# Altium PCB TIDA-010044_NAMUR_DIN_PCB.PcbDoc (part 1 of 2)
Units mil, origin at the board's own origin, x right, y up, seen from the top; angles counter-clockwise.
Board outline 1290 x 2860 mil, 2 copper layers (Top Layer, Bottom Layer), stack 62 mil thick; 85 components, 49 nets, 226 pads, 57 vias.
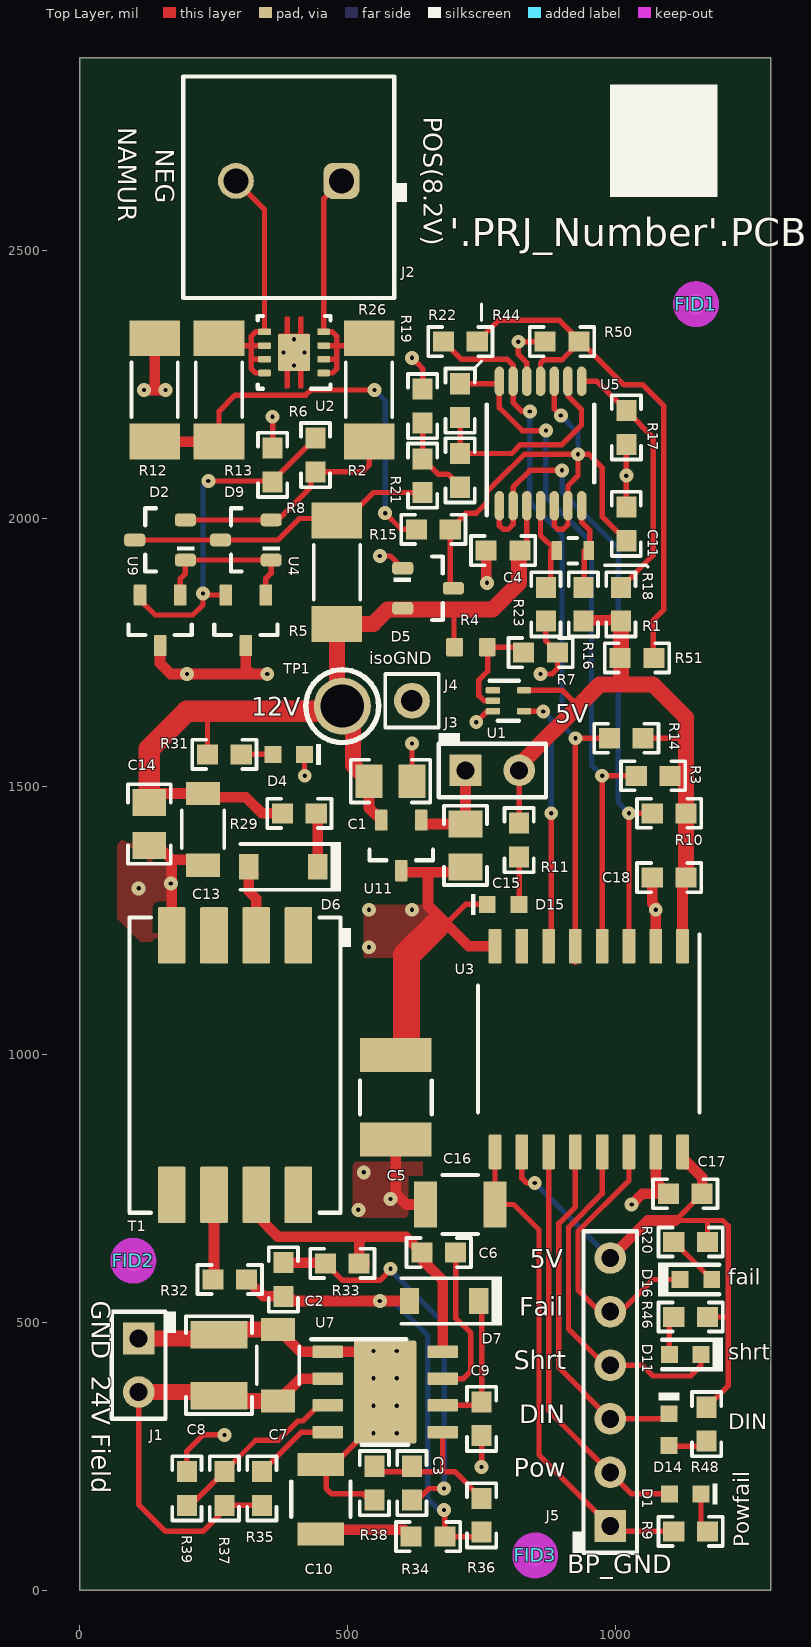
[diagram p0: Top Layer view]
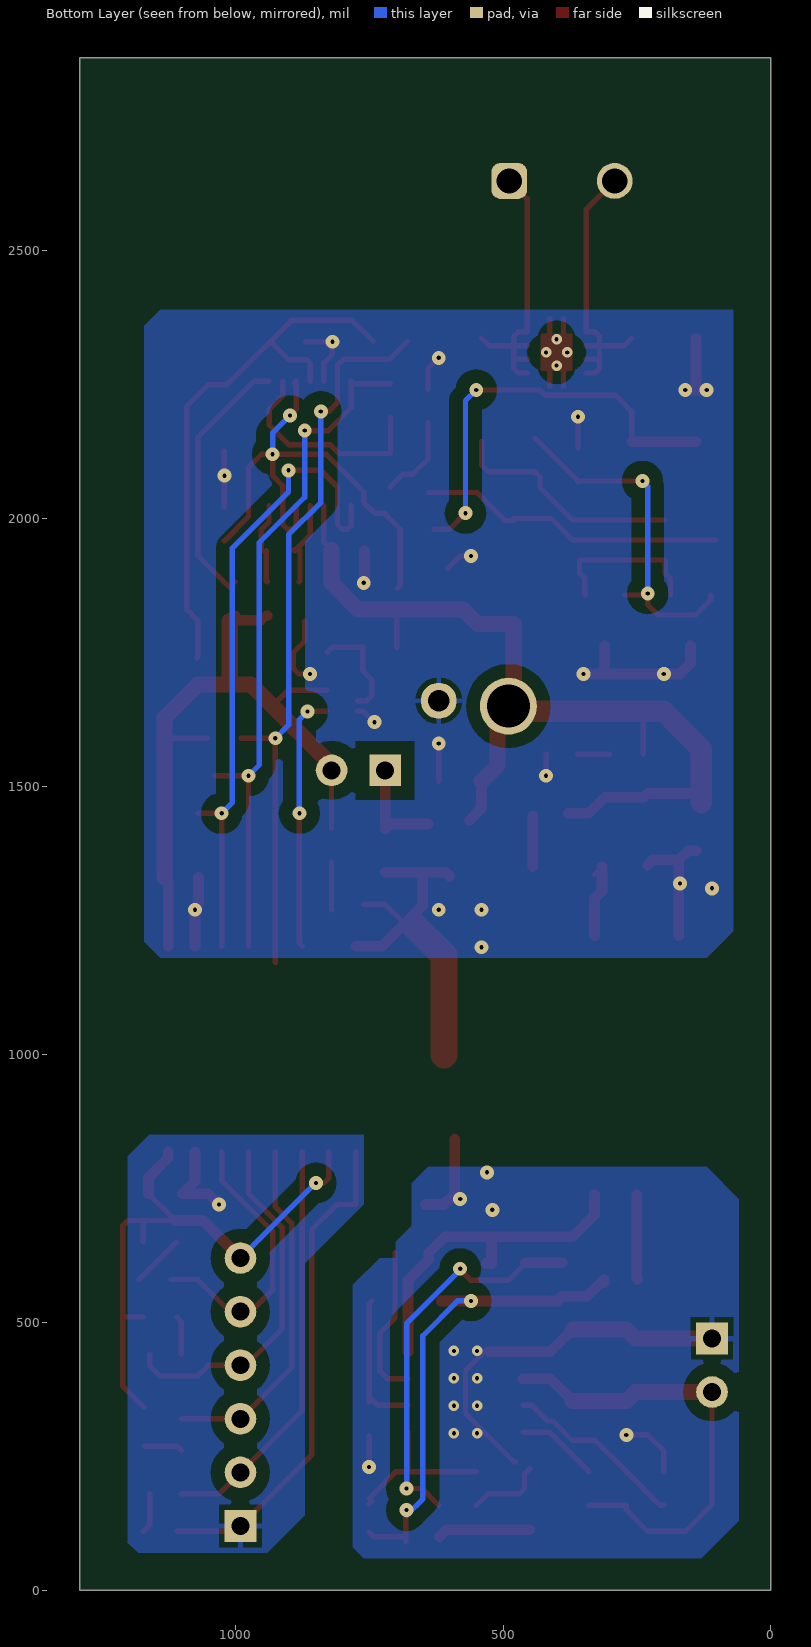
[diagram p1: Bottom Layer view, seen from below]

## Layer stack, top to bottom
Top Solder: solder mask 0.4, Solder Resist, Dk 3.5
Top Layer: signal copper 1.4
Dielectric1: core 59.2, FR-4, Dk 4.8
Bottom Layer: signal copper 1.4
Bottom Solder: solder mask 0.4, Solder Resist, Dk 3.5

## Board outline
0,0 1290,0 1290,2860 0,2860

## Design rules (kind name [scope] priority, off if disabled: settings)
AcuteAngle [All] p1: minimum=4.50000000000000E+0001 checktracksonly=FALSE
AssemblyTestPointUsage [All] p1: valid=2
BoardOutlineClearance BoardOutlineClearance_MountingHoles [OnCopper and InComponentClass('Mounting Holes')] p1: gap=40 ignorepadtopadclearanceinfootprint=FALSE
BoardOutlineClearance BoardOutlineClearance_Poly [OnCopper and IsPoly] p2: gap=25 ignorepadtopadclearanceinfootprint=FALSE
BoardOutlineClearance [OnCopper and Not InComponentClass('Logo') and not InComponentClass('FiducialMark') and not InRegion(1000,500,4000,800) and not InPoly] p3: gap=75 ignorepadtopadclearanceinfootprint=FALSE
Clearance Clearance_Keepouts [((IsTrack Or IsArc) And Not InPoly) And IsFree and IsKeepOut vs ((IsTrack Or IsArc) And Not InPoly) And IsFree and IsKeepOut] p1: gap=0 ignorepadtopadclearanceinfootprint=FALSE
Clearance Clearance_Poly [InPolygon] p2: gap=25 ignorepadtopadclearanceinfootprint=FALSE except(0: Arc-Hole Track-Hole SMDPad-Hole THPad-Hole Via-Hole Fill-Hole Poly-Hole Region-Hole Text-Hole)
Clearance Clearance_FiducialMark [IsKeepOut and InComponentClass('FiducialMark') vs IsPad and InComponentClass('FiducialMark')] p3: gap=0 ignorepadtopadclearanceinfootprint=FALSE
Clearance [All] p4: gap=7.87 ignorepadtopadclearanceinfootprint=FALSE except(0: Arc-Hole Track-Hole SMDPad-Hole THPad-Hole Via-Hole Fill-Hole Poly-Hole Region-Hole Text-Hole)
ComponentClearance ComponentClearance_MountingHoles_FiducialMarks [InComponentClass('Mounting Holes') vs InComponentClass('FiducialMark')] p1: gap=50 collisioncheckmode=3 verticalgap=10 showdistances=FALSE
ComponentClearance ComponentClearance_Shunt [InComponentClass('Header') vs InComponentClass('Shunt')] p2: gap=0 collisioncheckmode=3 verticalgap=0 showdistances=FALSE
ComponentClearance ComponentClearance_Logo [InComponentClass('Logo')] p3: gap=50 collisioncheckmode=3 verticalgap=10 showdistances=FALSE
ComponentClearance ComponentClearance_ScrewToNut [(HasFootprint('NY PMS 440 0025 PH')) vs (HasFootprint('Keystone_1902C'))] p4: gap=5 collisioncheckmode=3 verticalgap=10 showdistances=FALSE
ComponentClearance ComponentClearance_MountingHoles [InComponentClass('Mounting Holes')] p5: gap=250 collisioncheckmode=3 verticalgap=100000 showdistances=FALSE
ComponentClearance ComponentClearance_SmallPassives [HasFootprint('0201*') or HasFootprint('0402*') or HasFootprint('0508') or HasFootprint('0603*') or HasFootprint('0612') or HasFootprint('0805*') or HasFootprint('0815*') or HasFootprint('0830*') or HasFootprint('1206*') or HasFootprint('1210*') or HasFootprint('1808*') or HasFootprint('1812*') or HasFootprint('1825*') or HasFootprint('2010*') or HasFootprint('2220*') or HasFootprint('2225*') or HasFootprint('2512*') or HasFootprint('2728*') or HasFootprint('3518*') vs HasFootprint('0201*') or HasFootprint('0402*') or HasFootprint('0508') or HasFootprint('0603*') or HasFootprint('0612') or HasFootprint('0805*') or HasFootprint('0815*') or HasFootprint('0830*') or HasFootprint('1206*') or HasFootprint('1210*') or HasFootprint('1808*') or HasFootprint('1812*') or HasFootprint('1825*') or HasFootprint('2010*') or HasFootprint('2220*') or HasFootprint('2225*') or HasFootprint('2512*') or HasFootprint('2728*') or HasFootprint('3518*')] p6: gap=14.96 collisioncheckmode=3 verticalgap=10 showdistances=FALSE
ComponentClearance ComponentClearance_THtoSMT [IsThruComponent vs IsSMTComponent] p7: gap=40 collisioncheckmode=3 verticalgap=30 showdistances=FALSE
ComponentClearance ComponentClearance_THtoTH [IsThruComponent vs IsThruComponent] p8: gap=30 collisioncheckmode=3 verticalgap=30 showdistances=FALSE
ComponentClearance [All] p9: gap=30 collisioncheckmode=3 verticalgap=10 showdistances=FALSE
DiffPairsRouting [All] p1: maxlimit=100 minlimit=10 mostfreqgap=10 toplayer_minwidth=15 toplayer_maxwidth=15 toplayer_prefwidth=15 bottomlayer_minwidth=15 bottomlayer_maxwidth=15 bottomlayer_prefwidth=15 maxuncoupledlength=1000
FabricationTestPointUsage TestPointUsage [All] p1: valid=2 allowmultiple=FALSE
FabricationTestpoint Testpoint [All] p1: side=3 testpointundercomponent=TRUE minsize=40 maxsize=100 preferedsize=60 minholesize=0 maxholesize=40 preferedholesize=32 testpointgrid=1 allowsidetop=TRUE allowsidebottom=TRUE usegrid=TRUE gridtolerance=0.01
FanoutControl Fanout_LCC [IsLCC] p1: bgadir=Out bgaviamode=Centered fanoutstyle=Auto fanoutdirection=Alternating viagrid=1 // Fanout_LCC (Default Rule)
FanoutControl Fanout_BGA [IsBGA] p2: bgadir=Out bgaviamode=Centered fanoutstyle=Auto fanoutdirection=Alternating viagrid=1 // Fanout_BGA (Default Rule)
FanoutControl Fanout_Default [All] p4: bgadir=Out bgaviamode=Centered fanoutstyle=Auto fanoutdirection=Alternating viagrid=1 // Fanout_Default (Default Rule)
FanoutControl Fanout_Small [(CompPinCount < 5)] p5: bgadir=Out bgaviamode=Centered fanoutstyle=Auto fanoutdirection=OutThenIn viagrid=1 // Fanout_Small (Default Rule)
HoleSize [All] p1: absolutevalues=TRUE maxlimit=251 minlimit=7.87 maxpercent=80.000 minpercent=20.000
MinimumAnnularRing MinimumAnnularRing_ThermalPadVias [IsVia and InAnyComponent] p1: minimumring=5.91
MinimumAnnularRing [All] p2: minimumring=8
MinimumSolderMaskSliver MinimumSolderMaskSliver_Logo [InComponentClass('Logo') vs InComponentClass('Logo')] p1: minsoldermaskwidth=0.7
MinimumSolderMaskSliver [All] p2: minsoldermaskwidth=3.94
PlaneConnect [All] p1: planeconnectstyle=Relief reliefexpansion=10 reliefentries=4 reliefconductorwidth=10 reliefairgap=10
PolygonConnect [All] p1: thpad.connectstyle=Relief thpad.reliefconductorwidth=10 thpad.reliefentries=4 thpad.polygonreliefangle="90 Angle" thpad.airgapwidth=10 smdpad.connectstyle=Relief smdpad.reliefconductorwidth=10 smdpad.reliefentries=4 smdpad.polygonreliefangle="90 Angle" smdpad.airgapwidth=10 via.connectstyle=Direct via.reliefconductorwidth=10 via.reliefentries=4 via.polygonreliefangle="90 Angle" via.airgapwidth=10
RoutingVias ThermalPadVias [IsVia and InAnyComponent] p1: holewidth=7.87 width=19.68 viastyle="Through Hole" minholewidth=7.87 minwidth=19.68 maxholewidth=12.99 maxwidth=23.62
RoutingVias [All] p2: holewidth=16 width=34 viastyle="Through Hole" minholewidth=7.87 minwidth=26 maxholewidth=40 maxwidth=65
SilkToBoardRegionClearance [Not ((IsComment or IsDesignator) And (Hide <> 'False')) and not InRegion(1000,500,4000,800)] p1:
SilkToSilkClearance SilkToSilkClearance_Pb-FreeLogo [(HasFootprint('Pb-Free_Overlay_Medium') OR HasFootprint('Pb-Free_Overlay_Small')) vs (HasFootprint('Pb-Free_Overlay_Medium') OR HasFootprint('Pb-Free_Overlay_Small'))] p1: silktosilkclearance=0
SilkToSilkClearance [All] p2: silktosilkclearance=4
SilkToSolderMaskClearance SilkToComponentPadClearance [(IsPad or IsFill or IsRegion) and InAnycomponent] p1: minsilkscreentomaskgap=3.94 clearancetoexposedcopper=TRUE
SilkToSolderMaskClearance "Silk to Solder Mask Opening" [All] p2: minsilkscreentomaskgap=4 clearancetoexposedcopper=FALSE
SolderMaskExpansion [All] p1: expansion=1.97
Width [All] p1: maxlimit=100 minlimit=6 preferedwidth=10 checkconnectedcopper=TRUE
15 further rules are at their usual default settings.

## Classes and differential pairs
component class TIDA-010044_NAMUR_DIN_Power: C1 C2 C3 C5 C6 C7 C8 C9 C10 C13 C14 C15 C16 C17 C18 D1 D4 D6 D7 D11 D14 D15 D16 J1 J3 J4 J5 R4 R7 R9 R11 R20 R29 R31 R32 R33 R34 R35 R36 R37 R38 R39 R46 R48 T1 TP1 U1 U3 U7 U11
component class TIDA-010044_NAMUR_DIN_Input: C4 C11 D2 D5 D9 J2 R1 R2 R3 R5 R6 R8 R10 R12 R13 R14 R15 R16 R17 R18 R19 R21 R22 R23 R26 R44 R50 R51 U2 U4 U5 U9
component class Header: J1 J3 J5
component class FiducialMark: FID1 FID2 FID3
component class TIDA-010044_NAMUR_DIN_Hardware: FID1 FID2 FID3

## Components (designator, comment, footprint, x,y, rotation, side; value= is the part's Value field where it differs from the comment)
C1 "GCM21BR71H104KA37K" 0805_HV 580,1510 r0 top value=0.1uF
C2 "CGA3E2X7R2A472K080AA" 0603 380,580 r90 top value=4700pF
C3 "0603YC104JAT2A" 0603 620,200 r90 top value=0.1uF
C4 "06035C104JAT2A" 0603 790,1940 r0 top value=0.1uF
C5 "CMP-0009296-2" 1812_254 590,920 r90 top value=2200pF
C6 "C0603C103J5RACTU" 0603 670,630 r0 top value=0.01uF
C7 "C3216X7R2A474K160AA" 1206_180 370,420 r90 top value=0.47uF
C8 "HMK325B7225KN-T" 1210 260,420 r90 top value=2.2uF
C9 "GRM188R71E105KA12D" 0603 750,320 r270 top value=1uF
C10 "GCM32ER71C226KE19L" 1210_280 450,170 r90 top value=22uF
C11 "C0603C223K3RACTU" 0603 1020,1990 r90 top value=0.022uF
C13 "GRM31CR71H475KA12L" 1206_180 230,1420 r270 top value=4.7uF
C14 "GCM21BR71H104KA37K" 0805_HV 130,1430 r270 top value=0.1uF
C15 "GCM21BR71H104KA37K" 0805_HV 720,1390 r270 top value=0.1uF
C16 "202S41W222KV4E" 1210_280 710,720 r180 top value=2200pF
C17 "06035C104JAT2A" 0603 1130,740 r180 top value=0.1uF
C18 "06035C104JAT2A" 0603 1100,1330 r180 top value=0.1uF
D1 "LB Q39G-L2N2-35-1" "LB Q39G_BLUE" 1130,180 r0 top value=Blue
D2 "BAT54AFILM" SOT-23 150,1960 r180 top value=40V
D4 "CMP-0002849-2" "LB Q39G_BLUE" 390,1560 r0 top value=Blue
D5 "BAT54S-7-F" SOT-23 650,1870 r0 top value=30V
D6 "MMSD4148T1G" SOD-123 380,1350 r180 top value=100V
D7 "BAT42W-7-F" SOD-123 680,540 r180 top value=30V
D9 "BAT54AFILM" SOT-23 310,1960 r180 top value=40V
D11 "LTST-C190CKT" LED_LTST-C190_Red 1130,440 r0 top value=Red
D14 "LTST-C190KGKT" LED_LTST-C190_G 1100,300 r90 top value=Green
D15 "LB Q39G-L2N2-35-1" "LB Q39G_BLUE" 790,1280 r180 top value=Blue
D16 "LTST-C190KFKT" LED_LTST-C190 1150,580 r180 top value=Orange
FID1 "Fiducial" Fiducial10-20 1150,2400 r0 top
FID2 "Fiducial" Fiducial10-20 100,615 r0 top
FID3 "Fiducial" Fiducial10-20 850,65 r0 top
J1 "800-10-002-10-001000" Mill-Max_800-10-002-10-001000 110,420 r270 top
J2 "1792863" Phoenix_1792863 390,2630 r180 top
J3 "800-10-002-10-001000" Mill-Max_800-10-002-10-001000 770,1530 r0 top
J4 "TSW-101-17-T-S" Samtec_TSW-101-17-T-S 620,1660 r90 top
J5 "800-10-006-10-001000" Mill-Max_800-10-006-10-001000 990,370 r90 top
R1 "RT0603BRD074K12L" 0603 1010,1840 r270 top value=4.12k
R2 "MMB02070C4020FB200" MMB0207 540,2240 r90 top value=402
R3 "RC1608J103CS" 0603 1070,1520 r0 top value=10k
R4 "PTN0603E8351BST1" PTN_0603 730,1760 r180 top value=8.35k
R5 "MMB02070C4020FB200" MMB0207 480,1900 r90 top value=402
R6 "RT0603BRD0713K8L" 0603 440,2118.5 r270 top value=13.8k
R7 "RT0603BRD073K61L" 0603 860,1750 r180 top value=3.61k
R8 "RT0603DRE076K04L" 0603 360,2100 r270 top value=6.04k
R9 "CMP-0025906-5" 0603 1140,110 r0 top value=2.2k
R10 "RC0603JR-072K2L" 0603 1100,1450 r0 top value=2.2k
R11 "CMP-0025906-5" 0603 820,1400 r90 top value=2.2k
R12 "MMB02070C4990FB200" MMB0207 140,2240 r270 top value=499
R13 "CMB02070X1000GB200" MMB0207 260,2240 r90 top value=100
R14 "RC1608J103CS" 0603 1020,1590 r0 top value=10k
R15 "RC1608J103CS" 0603 660,1980 r180 top value=10k
R16 "RG1608P-7871-B-T5" 0603 940,1840 r270 top value=7.87k
R17 "RT0603BRD078K87L" 0603 1020,2170 r270 top value=8.87k
R18 "TNPW060310K0BEEA" TNPW0603 920,1940 r0 top value=10.0k
R19 "RT0603BRD072K21L" 0603 640,2080 r270 top value=2.21k
R20 "RC0603JR-073K3L" 0603 1140,650 r180 top value=3.3k
R21 "RT0603BRD071KL" 0603 710,2090 r90 top value=1.00k
R22 "RT0603BRD072K21L" 0603 640,2210 r270 top value=2.21k
R23 "RT0603BRD071KL" 0603 870,1840 r90 top value=1.00k
R26 "ERA-3AEB1822V" 0603 710.32,2330.32 r180 top value=18.2k
R29 "CMP-0025885-5" 0603 410,1450 r180 top value=0
R31 "RC0603JR-077K5L" 0603 270,1560 r180 top value=7.5k
R32 "CMP-0025885-5" 0603 280,580 r0 top value=0
R33 "RC0603FR-0746K4L" 0603 490,610 r180 top value=46.4k
R34 "CMP-0025885-5" 0603 650,100 r0 top value=0
R35 "RC0603FR-07499KL" 0603 340,190 r270 top value=499k
R36 "CRCW060382K5FKEA" 0603 750,140 r270 top value=82.5k
R37 "CRCW0603127KFKEA" 0603 270,190 r270 top value=127k
R38 "CRCW060313K7FKEA" 0603 550,200 r90 top value=13.7k
R39 "ERJ-3EKF1002V" 0603 200,190 r270 top value=10.0k
R44 "RC0603FR-0723K7L" 0603 710,2220 r90 top value=23.7k
R46 "RC0603JR-073K3L" 0603 1140,510 r180 top value=3.3k
R48 "RC0603JR-073K3L" 0603 1170,310 r270 top value=3.3k
R50 "RT0603BRD071KL" 0603 900,2330 r0 top value=1.00k
R51 "RT0603BRD075K62L" 0603 1040,1740 r0 top value=5.62k
T1 "750317030" Wurth_ER9_5S_6310 290,980 r270 top value=80uH
TP1 "12V_ISO" Keystone1573-2 490,1650 r90 top
U1 "SN74LVC1G14DRLR" DRL0005A 800,1660 r0 top
U2 "TVS3301DRBR" DRB0008A 400,2310 r180 top
U3 "ISO7340FCDWR" DW0016B_HV 950,1010 r270 top
U4 "TL431LIAQDBZR" DBZ0003A_N 310,1810 r270 top
U5 "LM2901AVQPWRQ1" PW0014A_N 860,2140 r90 top
U7 "LM25019MRX/NOPB" DDA0008B_N 570,370 r0 top
U9 "TL431LIAQDBZR" DBZ0003A_N 150,1810 r270 top
U11 "TLV76050DBZR" DBZ0003A_N 600,1390 r270 top

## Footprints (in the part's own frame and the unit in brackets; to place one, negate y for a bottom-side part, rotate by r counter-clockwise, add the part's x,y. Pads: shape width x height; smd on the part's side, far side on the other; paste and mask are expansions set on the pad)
0603 [mm] "0603 from SM-752 data"
  rect 1x0.95 smd: 1(-0.8,0) 2(0.8,0)
  silkscreen extent -1.52,-0.69 1.52,0.69, body extent -0.87,-0.47 0.87,0.47, height 1
0805_HV [mil] "0805 with 30mil clearance between pads"
  rect 50x63 smd: 1(-40,0) 2(40,0)
  silkscreen extent -74,-40 74,40, body extent -43,-29 43,29, height 57
1206_180 [mm] "1206_180"
  rect 1.1x1.6 smd: 1(-1.7,0) 2(1.7,0)
  silkscreen extent -0.9,-1 0.9,1, body extent -1.75,-0.95 1.75,0.95, height 1.8
1210 [mm] "1210 from SM-752 data"
  rect 1.3x2.7 smd: 1(-1.45,0) 2(1.45,0)
  silkscreen extent -2.32,-1.57 2.32,1.57, body extent -1.7,-1.35 1.7,1.35, height 1.35
1210_280 [mm] "SMD, 2-Leads, Body 3.6x2.8mm, Height 2.8mm"
  rect 1.1x2.2 smd: 1(-1.65,0) 2(1.65,0)
  silkscreen extent -0.84,-1.4 0.84,1.4, body extent -1.8,-1.4 1.8,1.4, height 2.8
1812_254 [mm] "SMD, 2-Leads, Body 4.8x3.4mm"
  rect 1.6x3.4 smd: 1(-2,0) 2(2,0)
  silkscreen extent -0.8,-1.7 0.8,1.7, body extent -2.4,-1.7 2.4,1.7, height 2.54
DBZ0003A_N [mm] "SOT23, 3-Leads, Body 2.9x1.3mm, Pitch 0.95mm, Lead Span 2.4mm, IPC Medium Density"
  rrect17% 1x0.6 smd: 1(-1.2,0.95) 2(-1.2,-0.95) 3(1.2,0)
  silkscreen extent 0.2,-1.5 0.7,1.5, body extent -1.26,-1.46 1.26,1.46, height 0.98
DDA0008B_N [mm] "SOIC, 8-Leads, Body 4.9x3.9mm, Pitch 1.27mm, Exposed Pad, IPC Medium Density"
  rrect17% 1.45x0.6 smd: 1(-2.725,1.905) 2(-2.725,0.635) 3(-2.725,-0.635) 4(-2.725,-1.905) 5(2.725,-1.905) 6(2.725,-0.635) 7(2.725,0.635) 8(2.725,1.905)
  rrect7% 2.95x4.9 smd paste-1.5 mask-1.5: 9(0,0)
  rrect4% 2.71x3.4 on Top Paste: 9(0,0)
  rrect4% 2.71x3.4 on Top Solder: 9(0,0)
  silkscreen extent -3.5,-2.5 1.1,2.5, body extent -3.01,-2.45 3.01,2.45, height 1.57
DRB0008A [mm] "VSON-8"
  rrect32% 0.6x0.31 smd: 1(-1.4,0.975) 2(-1.4,0.325) 3(-1.4,-0.325) 4(-1.4,-0.975) 5(1.4,-0.975) 6(1.4,-0.325) 7(1.4,0.325) 8(1.4,0.975)
  rrect7% 1.5x1.75 smd paste-0.75: 9(0,0)
  Top Layer region: -0.7,-0.875 -0.49,-0.875 -0.471,-0.879 -0.455,-0.89 -0.444,-0.906 -0.44,-0.925 -0.44,-0.925 -0.44,-1.65 -0.436,-1.669 -0.425,-1.685 -0.409,-1.696 -0.39,-1.7 -0.39,-1.7 -0.26,-1.7 -0.241,-1.696 -0.225,-1.685 -0.214,-1.669 -0.21,-1.65 -0.21,-1.65 -0.21,-0.925 -0.206,-0.906 -0.195,-0.89 -0.179,-0.879 -0.16,-0.875 -0.16,-0.875 0.16,-0.875 0.179,-0.879 0.195,-0.89 0.206,-0.906 0.21,-0.925 0.21,-0.925 0.21,-1.65 0.21,-1.65 0.214,-1.669 0.225,-1.685 0.241,-1.696 0.26,-1.7 0.26,-1.7 0.39,-1.7 0.409,-1.696 0.425,-1.685 0.436,-1.669 0.44,-1.65 0.44,-1.65 0.44,-0.925 0.444,-0.906 0.455,-0.89 0.471,-0.879 0.49,-0.875 0.49,-0.875 0.7,-0.875 0.719,-0.871 0.735,-0.86 0.746,-0.844 0.75,-0.825 0.75,-0.825 0.75,0.825 0.746,0.844 0.735,0.86 0.719,0.871 0.7,0.875 0.7,0.875 0.49,0.875 0.471,0.879 0.455,0.89 0.444,0.906 0.44,0.925 0.44,0.925 0.44,1.65 0.436,1.669 0.425,1.685 0.409,1.696 0.39,1.7 0.39,1.7 0.26,1.7 0.241,1.696 0.225,1.685 0.214,1.669 0.21,1.65 0.21,1.65 0.21,1.65 0.21,0.925 0.206,0.906 0.195,0.89 0.179,0.879 0.16,0.875 0.16,0.875 -0.16,0.875 -0.179,0.879 -0.195,0.89 -0.206,0.906 -0.21,0.925 -0.21,0.925 -0.21,1.65 -0.214,1.669 -0.225,1.685 -0.241,1.696 -0.26,1.7 -0.26,1.7 -0.39,1.7 -0.409,1.696 -0.425,1.685 -0.436,1.669 -0.44,1.65 -0.44,1.65 -0.44,0.925 -0.444,0.906 -0.455,0.89 -0.471,0.879 -0.49,0.875 -0.49,0.875 -0.7,0.875 -0.719,0.871 -0.735,0.86 -0.746,0.844 -0.75,0.825 -0.75,0.825 -0.75,-0.825 -0.746,-0.844 -0.735,-0.86 -0.719,-0.871 -0.7,-0.875
  silkscreen extent -1.73,-1.73 1.73,1.73, body extent -1.5,-1.5 1.5,1.5, height 0.77
DRL0005A [mm] "SOTFL, 5-Flat Leads, Body 1.2x1.6x0.6mm, Pitch 0.5mm, TI recommended"
  rrect33% 0.67x0.3 smd: 1(-0.74,0.5) 2(-0.74,0) 3(-0.74,-0.5) 4(0.74,-0.5) 5(0.74,0.5)
  silkscreen extent -0.9,-0.95 0.5,0.95, body extent -0.85,-0.85 0.85,0.85, height 0.62
DW0016B_HV [mm] "High voltage version of DW0016B"
  rrect17% 1.65x0.6 smd: 1(-4.875,4.445) 2(-4.875,3.175) 3(-4.875,1.905) 4(-4.875,0.635) 5(-4.875,-0.635) 6(-4.875,-1.905) 7(-4.875,-3.175) 8(-4.875,-4.445) 9(4.875,-4.445) 10(4.875,-3.175) 11(4.875,-1.905) 12(4.875,-0.635) 13(4.875,0.635) 14(4.875,1.905) 15(4.875,3.175) 16(4.875,4.445)
  silkscreen extent -5.43,-5.25 3,5.25, body extent -5.14,-5.13 5.14,5.13, height 2.5
Fiducial10-20 [mm]
  round 1 smd mask+0.5: 1(0,0)
  Top Layer keep-out circle w1.178: c0,0 r0.5
Keystone1573-2 [mm] "Double Turret"
  round 2.7 hole 2.05: 1(0,0)
  silkscreen extent -1.73,-1.73 1.73,1.73, body extent -1.18,-1.18 1.17,1.18, height 4.72
"LB Q39G_BLUE" [mm] "OSRAM"
  rect 0.8x0.8 smd: 1(-0.75,0) 2(0.75,0)
  silkscreen extent 1.3,-0.5 1.52,0.5, body extent -0.85,-0.45 0.85,0.45, height 0.4
LED_LTST-C190 [mm] "Lite-On"
  rect 0.8x0.8 smd: 1(-0.75,0) 2(0.75,0)
  silkscreen extent -1.1,-0.8 1.8,0.8, body extent -0.85,-0.45 0.85,0.45, height 0.9
LED_LTST-C190_G [mm] "Lite-On"
  rect 0.8x0.8 smd: 1(-0.75,0) 2(0.75,0)
  silkscreen extent 1.37,-0.5 1.75,0.5, body extent -0.85,-0.45 0.85,0.45, height 0.9
LED_LTST-C190_Red [mm] "Lite-On"
  rect 0.8x0.8 smd: 1(-0.75,0) 2(0.75,0)
  silkscreen extent -1.1,-0.8 1.8,0.8, body extent -0.85,-0.45 0.85,0.45, height 0.9
Mill-Max_800-10-002-10-001000 [mm] "Mill-Max"
  rect 1.5x1.5 hole 0.85: 1(-1.27,0)
  round 1.5 hole 0.85: 2(1.27,0)
  silkscreen extent -2.54,-1.27 2.54,1.78, body extent -2.54,-1.27 2.54,1.27, height 8.13
Mill-Max_800-10-006-10-001000 [mm] "Mill-Max"
  rect 1.5x1.5 hole 0.85: 1(-6.35,0)
  round 1.5 hole 0.85: 2(-3.81,0) 3(-1.27,0) 4(1.27,0) 5(3.81,0) 6(6.35,0)
  silkscreen extent -7.62,-1.27 7.62,1.78, body extent -7.62,-1.27 7.62,1.27, height 8.13
MMB0207 [mm] "Vishay Beyschlag"
  rect 1.7x2.4 smd: 1(-2.45,0) 2(2.45,0)
  silkscreen extent -1.3,-1.1 1.3,1.1, body extent -2.98,-1.1 2.98,1.1, height 2.2
Phoenix_1792863 [mm] "Terminal Block, 5mm, 2x1, R/A, TH"
  rrect50% 1.7x1.7 hole 1.2: 1(-2.5,0)
  round 1.7 hole 1.2: 2(2.5,0)
  silkscreen extent -5.6,-4.95 5,5.55, body extent -5,-4.95 5,5.55, height 13.6
PTN_0603 [mil] "SMD, 2-Leads, Body 64x32mil"
  rrect13% 31x34 smd: 1(-30.5,0) 2(30.5,0)
  body extent -35,-19 35,19, height 20
PW0014A_N [mm] "TSOP, 14-Leads, Body 5x4.4mm, Pitch 0.65mm, IPC Medium Density"
  oval 1.4x0.45 smd: 1(-2.95,1.95) 2(-2.95,1.3) 3(-2.95,0.65) 4(-2.95,0) 5(-2.95,-0.65) 6(-2.95,-1.3) 7(-2.95,-1.95) 8(2.95,-1.95) 9(2.95,-1.3) 10(2.95,-0.65) 11(2.95,0) 12(2.95,0.65) 13(2.95,1.3) 14(2.95,1.95)
  silkscreen extent -3.4,-2.55 1.85,2.55, body extent -3.21,-2.5 3.21,2.5, height 1
Samtec_TSW-101-17-T-S [mm] "Samtec,CONN HEADER 1POS .100\" SNGL TIN"
  round 1.7 hole 1.02: 1(0,0)
  silkscreen extent -1.27,-1.27 1.27,1.27, body extent -1.27,-1.27 1.27,1.27, height 18.29
SOD-123 [mm] "On Semi recommended land pattern"
  rect 0.915x1.22 smd: 1(-1.637,0) 2(1.637,0)
  silkscreen extent -2.74,-1.17 2.03,1.17, body extent -1.93,-0.9 1.93,0.9, height 1.35
SOT-23 [mm] "SOT23, 3-Leads, Body 2.9x1.3mm, Pitch 0.95mm, Lead Span 2.5mm, IPC Medium Density"
  rrect50% 1x0.6 smd: 1(-1.2,0.95) 2(-1.2,-0.95) 3(1.2,0)
  silkscreen extent -1.62,-1.5 0.7,1.5, body extent -1.16,-1.45 1.21,1.45, height 1
TNPW0603 [mm] "Vishay"
  rect 0.5x0.9 smd: 1(-0.75,0) 2(0.75,0)
  silkscreen extent -0.2,-0.6 0.2,0.6, body extent -0.85,-0.47 0.85,0.47, height 0.55
Wurth_ER9_5S_6310 [mm] "SMT, 8-Leads, Body 10x14mm"
  rrect8% 2.67x1.31 smd: 1(-6.15,3) 2(-6.15,1) 3(-6.15,-1) 4(-6.15,-3) 5(6.15,-3) 6(6.15,-1) 7(6.15,1) 8(6.15,3)
  silkscreen extent -7,-5 7,5.5, body extent -6.58,-4.75 6.58,4.75, height 4.83

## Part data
C1 C14 C15: library part CMP-0008021-2, "CAP, CERM, 0.1 uF, 50 V, +/- 10%, X7R, AEC-Q200 Grade 1, 0805", Cap_Case=0805, Manufacturer=MuRata, Supplier Part Number 1=490-8049-1-ND, TempCo=X7R, Tolerance_%=10%, Value1=Unknown, Value2=50V, ValueDisplayed=0.1uF
C2: library part CMP-0007088-4, "CAP, CERM, 4700 pF, 100 V, +/- 10%, X7R, AEC-Q200 Grade 1, 0603", Cap_Case=0603, Manufacturer=TDK, Supplier Part Number 1=445-5810-1-ND, TempCo=X7R, Tolerance_%=10%, Value1="0.469862 ohm", Value2=100V, ValueDisplayed=4700pF
C3: library part CMP-0006808-4, "CAP, CERM, 0.1 uF, 16 V, +/- 5%, X7R, 0603", Cap_Case=0603, Manufacturer=AVX, Supplier Part Number 1=478-3726-1-ND, TempCo=X7R, Tolerance_%=5%, Value1="0.039 ohm", Value2=16V, ValueDisplayed=0.1uF
C4 C17 C18: library part CMP-0083854-1, "CAP, CERM, 0.1 µF, 50 V,+/- 5%, X7R, 0603", Cap_Case=0603, Manufacturer=AVX, TempCo=X7R, Tolerance_%=5%, Value2=50V, ValueDisplayed=0.1µF
C5: "CAP, CERM, 2200 pF, 3000 V, +/- 10%, X7R, 1812", Cap_Case=1812, Manufacturer=AVX, PartNumber=1812HC222KAT1A, Supplier Part Number 1=478-4733-1-ND, TempCo=X7R, Tolerance_%=10%, Value1=Unknown, Value2=3000V, ValueDisplayed=2200pF
C6: library part CMP-0006850-4, "CAP, CERM, 0.01 uF, 50 V, +/- 5%, X7R, 0603", Cap_Case=0603, Manufacturer=Kemet, Supplier Part Number 1=399-1092-1-ND, TempCo=X7R, Tolerance_%=5%, Value1=Unknown, Value2=50V, ValueDisplayed=0.01uF
C7: library part CMP-0008716-2, "CAP, CERM, 0.47 uF, 100 V, +/- 10%, X7R, 1206", Cap_Case=1206_180, Manufacturer=TDK, Supplier Part Number 1=445-2284-1-ND, TempCo=X7R, Tolerance_%=10%, Value1="0.007558 ohm", Value2=100V, ValueDisplayed=0.47uF
C8: library part CMP-0009253-2, "CAP, CERM, 2.2 uF, 100 V, +/- 10%, X7R, 1210", Cap_Case=1210, Manufacturer="Taiyo Yuden", Supplier Part Number 1=587-1778-1-ND, TempCo=X7R, Tolerance_%=10%, Value1=Unknown, Value2=100V, ValueDisplayed=2.2uF
C9: library part CMP-0007405-4, "CAP, CERM, 1 uF, 25 V, +/- 10%, X7R, 0603", Cap_Case=0603, Manufacturer=MuRata, Supplier Part Number 1=490-5307-1-ND, TempCo=X7R, Tolerance_%=10%, Value1=Unknown, Value2=25V, ValueDisplayed=1uF
C10: library part CMP-0009174-2, "CAP, CERM, 22 uF, 16 V, +/- 10%, X7R, 1210", Cap_Case=1210, Manufacturer=MuRata, Supplier Part Number 1=490-5242-1-ND, TempCo=X7R, Tolerance_%=10%, Value1=Unknown, Value2=16V, ValueDisplayed=22uF
C11: library part CMP-0006899-4, "CAP, CERM, 0.022 uF, 25 V, +/- 10%, X7R, 0603", Cap_Case=0603, Manufacturer=Kemet, Supplier Part Number 1=399-1094-1-ND, TempCo=X7R, Tolerance_%=10%, Value1=Unknown, Value2=25V, ValueDisplayed=0.022uF
C13: library part CMP-0008969-2, "CAP, CERM, 4.7 uF, 50 V, +/- 10%, X7R, 1206", Cap_Case=2220, Manufacturer=MuRata, Supplier Part Number 1=24R6347, TempCo=X7R, Tolerance_%=10%, Value1=Unknown, Value2=50V, ValueDisplayed=4.7uF
C16: library part CMP-0009070-1, "CAP, CERM, 2200 pF, 2000 V, +/- 10%, X7R, 1210", Cap_Case=1210, Manufacturer="Johanson Technology", Supplier Part Number 1=709-1307-1-ND, TempCo=X7R, Tolerance_%=10%, Value1=Unknown, Value2=2000V, ValueDisplayed=2200pF
D1 D15: library part CMP-0002849-2, "LED, Blue, SMD", Color=blue, Manufacturer=OSRAM, Value1=W, Value2=2.85V
D2 D9: library part CMP-0028619-2, "Diode, Schottky, 40 V, 0.3 A, SOT-23", Manufacturer=STMicroelectronics, Value1=0.3A, Value2=0.9V
D4: "LED, Blue, SMD", Color=blue, Manufacturer=OSRAM, PartNumber="LB Q39G-L2N2-35-1", Value1=W, Value2=2.85V
D5: library part CMP-0028456-2, "Diode, Schottky, 30 V, 0.2 A, SOT-23", Manufacturer="Diodes Inc.", Value1=0.2A, Value2=0.65V
D6: library part CMP-0029032-2, "Diode, Switching, 100 V, 0.2 A, SOD-123", Manufacturer="ON Semiconductor", Value1=0.2A, Value2=1V
D7: library part CMP-0028446-2, "Diode, Schottky, 30 V, 0.2 A, SOD-123", Manufacturer="Diodes Inc.", Value1=0.2A, Value2=1V
D11: library part CMP-0002842-2, "LED, Red, SMD", Color=red, Manufacturer=Lite-On, Power_TotalModule=62.5mW, Value1=0.0625W, Value2=2V
D14: library part CMP-0002840-2, "LED, Green, SMD", Color=green, Manufacturer=Lite-On, Value1=W, Value2=2V
D16: library part CMP-0002826-2, "LED, Orange, SMD", Color=orange, Manufacturer=Lite-On, Power_TotalModule=75mW, Supplier Part Number 1=160-1434-1-ND, Value1=0.075W, Value2=2V
FID1 FID2 FID3: library part CMP-0077181-1, "Fiducial mark.  There is nothing to buy or mount.", Manufacturer=N/A
J1 J3: library part CMP-0055085-1, "Header, 100mil, 2x1, TH", Manufacturer=Mill-Max, Supplier Part Number 1=ED7202-ND
J2: library part CMP-0055529-1, "Terminal Block, 5mm, 2x1, R/A, TH", Color=Green, Current_A=16A, Manufacturer="Phoenix Contact", Supplier Part Number 1=277-2518-ND, Voltage_V=400V
J4: library part CMP-0055993-1, "Header, 100mil, 1x1, Tin, TH", Color=Black, Current_A=6.3A, Manufacturer=Samtec, Supplier Part Number 1=SAM1067-01-ND, Voltage_V=550V
J5: library part CMP-0055084-1, "Header, 100mil, 6x1, TH", Manufacturer=Mill-Max, Supplier Part Number 1=ED7206-ND
R1: library part CMP-0024288-2, "RES, 4.12 k, 0.1%, 0.1 W, 0603", Manufacturer="Yageo America", Power_W=100mW, TempCo="25 ppm/C", Tolerance_%=0.1%, Value2=0.1W, Value_Code=4k12, ValueDisplayed=4.12k
R2 R5: library part CMP-0077149-1, "RES, 402, 1%, 1 W, AEC-Q200 Grade 0, 2.2x5.8mm", Manufacturer=Vishay/Beyschlag, Power_W=1W, Supplier Part Number 1=MMB02070C4020FB200-ND, TempCo="50 ppm/C", Tolerance_%=1%, Value_Code=402R, ValueDisplayed=402
R3 R14 R15: library part CMP-0025945-3, "RES, 10 k, 5%, 0.1 W, 0603", Manufacturer="Samsung Electro-Mechanics", Power_W=100mW, Supplier Part Number 1=1276-5086-1-ND, TempCo="100 ppm/C", Tolerance_%=5%, Value2=0.1W, Value_Code=10k0, ValueDisplayed=10k
R4: library part CMP-0080036-2, "RES, 8.35 k, 0.1%, 0.15 W, Body 64x32mil", Manufacturer="Vishay Thin Film", Power_W=150mW, Supplier Part Number 1=764-1461-1-ND, TempCo="25 ppm/C", Tolerance_%=0.1%, Value2=0.15W, Value_Code=8k35, ValueDisplayed=8.35k
R6: library part CMP-0023734-2, "RES, 13.8 k, 0.1%, 0.1 W, 0603", Manufacturer="Yageo America", Power_W=100mW, TempCo="25 ppm/C", Tolerance_%=0.1%, Value2=0.1W, Value_Code=13k8, ValueDisplayed=13.8k
R7: library part CMP-0024201-2, "RES, 3.61 k, 0.1%, 0.1 W, 0603", Manufacturer="Yageo America", Power_W=100mW, TempCo="25 ppm/C", Tolerance_%=0.1%, Value2=0.1W, Value_Code=3k61, ValueDisplayed=3.61k
R8: library part CMP-0025513-2, "RES, 6.04 k, 0.5%, 0.1 W, 0603", Manufacturer="Yageo America", Power_W=100mW, TempCo="50 ppm/C", Tolerance_%=0.5%, Value2=0.1W, Value_Code=6k04, ValueDisplayed=6.04k
R9 R11: "RES, 2.2 k, 5%, 0.1 W, 0603", Manufacturer=Yageo, PartNumber=RC0603JR-072K2L, Power_W=100mW, Supplier Part Number 1=311-2.2KGRCT-ND, TempCo="100 ppm/C", Tolerance_%=5%, Value2=0.1W, Value_Code=2k20, ValueDisplayed=2.2k
R10: library part CMP-0025906-5, "RES, 2.2 k, 5%, 0.1 W, 0603", Manufacturer=Yageo, Power_W=100mW, Supplier Part Number 1=311-2.2KGRCT-ND, TempCo="100 ppm/C", Tolerance_%=5%, Value2=0.1W, Value_Code=2k20, ValueDisplayed=2.2k
R12: library part CMP-0077150-1, "RES, 499, 1%, 1 W, AEC-Q200 Grade 0, 2.2x5.8mm", Manufacturer=Vishay/Beyschlag, Power_W=1W, Supplier Part Number 1=MMB02070C4990FB200-ND, TempCo="50 ppm/C", Tolerance_%=1%, Value_Code=499R, ValueDisplayed=499
R13: library part CMP-0077148-1, "RES, 100, 2%, 1 W, AEC-Q200 Grade 0, 2.2x5.8mm", Manufacturer=Vishay/Beyschlag, Power_W=1W, Supplier Part Number 1=CMB-100CT-ND, TempCo=ppm/C, Tolerance_%=2%, Value_Code=100R, ValueDisplayed=100
R16: library part CMP-0023602-3, "RES, 7.87 k, 0.1%, 0.1 W, 0603", Manufacturer="Susumu Co Ltd", Power_W=100mW, Supplier Part Number 1=RG16P7.87KBCT-ND, TempCo="25 ppm/C", Tolerance_%=0.1%, Value2=0.1W, Value_Code=7k87, ValueDisplayed=7.87k
R17: library part CMP-0024525-1, "RES, 8.87 k, 0.1%, 0.1 W, 0603", Manufacturer="Yageo America", Power_W=100mW, TempCo="25 ppm/C", Tolerance_%=0.1%, Value2=0.1W, Value_Code=8k87, ValueDisplayed=8.87k
R18: library part CMP-0025686-1, "RES, 10.0 k, 0.1%, 0.1 W, AEC-Q200 Grade 1, 0603", Manufacturer=Vishay-Dale, Power_W=100mW, Supplier Part Number 1=TNP10.0KAACT-ND, TempCo="25 ppm/C", Tolerance_%=0.1%, Value2=0.1W, Value_Code=10k0, ValueDisplayed=10.0k
R19 R22: library part CMP-0024063-3, "RES, 2.21 k, 0.1%, 0.1 W, 0603", Manufacturer="Yageo America", Power_W=100mW, TempCo="25 ppm/C", Tolerance_%=0.1%, Value2=0.1W, Value_Code=2k21, ValueDisplayed=2.21k
R20 R46 R48: library part CMP-0025918-5, "RES, 3.3 k, 5%, 0.1 W, 0603", Manufacturer=Yageo, Power_W=100mW, Supplier Part Number 1=311-3.3KGRCT-ND, TempCo="100 ppm/C", Tolerance_%=5%, Value2=0.1W, Value_Code=3k30, ValueDisplayed=3.3k
R21 R23 R50: library part CMP-0023919-1, "RES, 1.00 k, 0.1%, 0.1 W, 0603", Manufacturer="Yageo America", Power_W=100mW, Supplier Part Number 1=603-RT0603BRD071KL, TempCo="25 ppm/C", Tolerance_%=0.1%, Value2=0.1W, Value_Code=1k00, ValueDisplayed=1.00k
R26: library part CMP-0023370-2, "RES, 18.2 k, 0.1%, 0.1 W, AEC-Q200 Grade 0, 0603", Manufacturer=Panasonic, Power_W=100mW, Supplier Part Number 1=P18.2KDBCT-ND, TempCo="25 ppm/C", Tolerance_%=0.1%, Value2=0.1W, Value_Code=18k2, ValueDisplayed=18.2k
R29 R32 R34: "RES, 0, 5%, 0.1 W, 0603", Manufacturer=Yageo, PartNumber=RC0603JR-070RL, Power_W=100mW, Supplier Part Number 1=311-0.0GRCT-ND, TempCo="200 ppm/C", Tolerance_%=5%, Value2=0.1W, Value_Code=0000, ValueDisplayed=0
R31: library part CMP-0025940-5, "RES, 7.5 k, 5%, 0.1 W, 0603", Manufacturer=Yageo, Power_W=100mW, Supplier Part Number 1=311-7.5KGRCT-ND, TempCo="100 ppm/C", Tolerance_%=5%, Value2=0.1W, Value_Code=7k50, ValueDisplayed=7.5k
R33: library part CMP-0023126-5, "RES, 46.4 k, 1%, 0.1 W, 0603", Manufacturer=Yageo, Power_W=100mW, Supplier Part Number 1=311-46.4KHRCT-ND, TempCo="100 ppm/C", Tolerance_%=1%, Value2=0.1W, Value_Code=46k4, ValueDisplayed=46.4k
R35: library part CMP-0023140-4, "RES, 499 k, 1%, 0.1 W, 0603", Manufacturer=Yageo, Power_W=100mW, Supplier Part Number 1=311-499KHRCT-ND, TempCo="100 ppm/C", Tolerance_%=1%, Value2=0.1W, Value_Code=499k
R36: library part CMP-0022620-2, "RES, 82.5 k, 1%, 0.1 W, 0603", Manufacturer=Vishay-Dale, Power_W=100mW, Supplier Part Number 1=541-82.5KHCT-ND, TempCo="100 ppm/C", Tolerance_%=1%, Value2=0.1W, Value_Code=82k5, ValueDisplayed=82.5k
R37: library part CMP-0022028-4, "RES, 127 k, 1%, 0.1 W, AEC-Q200 Grade 0, 0603", Manufacturer=Vishay-Dale, Power_W=100mW, Supplier Part Number 1=541-127KHCT-ND, TempCo="100 ppm/C", Tolerance_%=1%, Value2=0.1W, Value_Code=127k
R38: library part CMP-0022044-2, "RES, 13.7 k, 1%, 0.1 W, 0603", Manufacturer=Vishay-Dale, Power_W=100mW, Supplier Part Number 1=541-13.7KHCT-ND, TempCo="100 ppm/C", Tolerance_%=1%, Value2=0.1W, Value_Code=13k7, ValueDisplayed=13.7k
R39: library part CMP-0022684-2, "RES, 10.0 k, 1%, 0.1 W, 0603", Manufacturer=Panasonic, Power_W=100mW, Supplier Part Number 1=P10.0KHCT-ND, TempCo="100 ppm/C", Tolerance_%=1%, Value2=0.1W, Value_Code=10k0, ValueDisplayed=10.0k
R44: library part CMP-0022934-5, "RES, 23.7 k, 1%, 0.1 W, 0603", Manufacturer=Yageo, Power_W=100mW, Supplier Part Number 1=311-23.7KHRCT-ND, TempCo="100 ppm/C", Tolerance_%=1%, Value2=0.1W, Value_Code=23k7, ValueDisplayed=23.7k
R51: library part CMP-0024374-1, "RES, 5.62 k, 0.1%, 0.1 W, 0603", Manufacturer="Yageo America", Power_W=100mW, TempCo="25 ppm/C", Tolerance_%=0.1%, Value2=0.1W, Value_Code=5k62, ValueDisplayed=5.62k
T1: library part CMP-0077153-3, "Transformer, 80 uH, SMT", Manufacturer="Wurth Elektronik", ValueDisplayed=80µH
TP1: library part CMP-0055119-1, "Terminal, Turret, TH, Double", Manufacturer=Keystone, PartNumber=1573-2, Supplier Part Number 1=36-1573-2-ND
U1: library part CMP-0051645-2, "Single Schmitt-Trigger Inverter, DRL0005A, LARGE T&R", Alternate Manufacturer="Texas Instruments", F @ Nom Voltage(Max)(Mhz)=150, Generic Part Number=SN74LVC1G14, ICC @ Nom Voltage(Max)(mA)=0.01, Operating Temperature Range(C)="-40 to 125,-40 to 85", Rating=Catalog, tpd @ Nom Voltage(Max)(ns)=11,6.5,5.5,5, Voltage(Nom)(V)=1.8,2.5,3.3,5
U2: library part CMP-0081715-3, "33 V Bidirectional Flat-Clamp Surge Protection Device, DRB0008A (VSON-8)", Alternate Manufacturer="Texas Instruments", Alternate PartNumber=TVS3301DRBT, Operating Temperature Range="-40 to 125 C", Rating=Catalog
U3: library part CMP-0065832-2, "Robust EMC, Low Power, Quad-Channel 4/0 Digital Isolator, Fail-Safe Low, DW0016B (SOIC-16)", Alternate Manufacturer="Texas Instruments", Alternate PartNumber=ISO7340FCDW
U4 U9: library part CMP-0084728-1, "Programmable Shunt Regulator with Optimized Reference Current, DBZ0003A (SOT-23-3)", Alternate Manufacturer="Texas Instruments"
U5: library part CMP-0065405-1, "Automotive Catalog Quad Differential Comparator, PW0014A (TSSOP-14)", Alternate Manufacturer="Texas Instruments"
U7: library part CMP-0066058-2, "7.5-48V Wide Vin, 100mA Constant On-Time Synchronous Buck Regulator, DDA0008B (SOIC-8)", Alternate Manufacturer="Texas Instruments", Alternate PartNumber=LM25019MR/NOPB
U11: library part CMP-0074892-1, "100-mA, 30-V, Fixed-Output, Linear-Voltage Regulator, DBZ0003A (SOT-23-3)", Alternate Manufacturer="Texas Instruments", Alternate PartNumber=TLV76050DBZT

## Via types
v1: diameter 26, hole 7.87, Top Layer to Bottom Layer, tented both sides, 44 vias
v2: diameter 19.68, hole 7.87, Top Layer to Bottom Layer, 8 vias
v3: diameter 19.68, hole 7.87, Top Layer to Bottom Layer, tented both sides, 4 vias
v4: diameter 26/26 (per signal layer), hole 7.87, Top Layer to Bottom Layer, tented both sides, 1 vias

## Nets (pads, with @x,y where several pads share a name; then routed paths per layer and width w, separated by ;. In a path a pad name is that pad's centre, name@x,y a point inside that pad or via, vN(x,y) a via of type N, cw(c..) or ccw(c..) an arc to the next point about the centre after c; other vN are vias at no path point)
BP_GND: C16.1 C17.2 J5.1 R9.1 U3.9 U3.15 | length 1120.9
  Top Layer w10: U3.9@775,792.13 U3.9@775,818.07 774.96,818.03 C16.1@774.96,720 810,720 857.13,672.87 857.13,252.87 J5.1@990,120 1000,110 R9.1@1108.5,110
  Top Layer w20: v1(1030,720) 1050,740 C17.2@1098.5,740 1075,763.5 U3.15@1075,818.07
